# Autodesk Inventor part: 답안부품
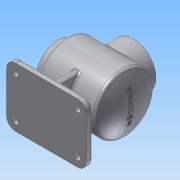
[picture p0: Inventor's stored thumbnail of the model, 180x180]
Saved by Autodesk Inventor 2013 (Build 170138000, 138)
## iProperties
Created: 2016-09
Part Number: 답안부품
Material: 알루미늄 6061
Document SubType Name: Modeling
Designer: Administrator
Density: 2.71 g/cm^3
Mass: 972.013 g
Surface Area: 1284.21 cm^2
Volume: 358.676 cm^3
Author: Administrator
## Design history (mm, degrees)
sketch "스케치1"
  geometry: L1 (-61, 0)-(61, 0); L2 (-61, 38)-(-49, 38); L3 (-49, 38)-(-49, 50); L4 (-49, 50)-(49.562, 50); L5 (-61, 38)-(-61, 27); L6 (47.661, 47)-(-46, 47); L7 (-46, 47)-(-46, 27); L8 (-61, 27)-(-46, 27); A1 r 115 centre (-54, 0) between (61, 0) and (49.562, 50); A2 r 112 centre (-54, 0) between (58, 0) and (47.661, 47); 2 further points
  constraints: 16 end point, 4 point on circle, 3 perpendicular, 2 centre point, 2 coincident, 2 parallel, 1 horizontal, 1 horizontal alignment, 1 midpoint, 1 point on line, 1 vertical alignment
  dimensions: "d0" = 76 diameter of L2 L1; "d2" = 100 diameter of L4 L1; "d3" = 12 distance of L2.start L2.end; "d7" = 115 radius of A1; "d8" = 110 horizontal distance of L1.end L2.end; "d9" = 3 radial gap between concentric circles of A1 A2; "d10" = 3 distance between parallel lines of L4 L6; "d11" = 54 diameter of L8 L1; "d12" = 3 distance between parallel lines of L3 L7
revolve "회전1" sketch "스케치1" stored, may be unused: angle "d13" = 90 deg
chamfer "모따기1" distance "d14" = 1; stored, may be unused: second distance "d15" = 2, angle "d16" = 45 deg
fillet "모깎기1" dims "d17" = 3
fillet "모깎기2" dims "d18" = 5
fillet "모깎기3" dims "d19" = 5
fillet "모깎기4" dims "d20" = 2
sketch "스케치2"
  geometry: C1 r 38 at (0, 0) reference; C2 r 28 at (0, 0) reference; A1 r 32.5 centre (0, 0) between (0, 32.5) and (0, -32.5); 2 further points
  constraints: 4 point on circle, 2 horizontal alignment, 2 vertical alignment, 1 centre point, 1 coincident
  dimensions: "d21" = 65 diameter of A1
hole "구멍1" sketch "스케치2" at (0, 32.5), (0, -32.5), (32.5, 0), (-32.5, 0) diameter "d23" = 3.242; stored, may be unused: countersink angle "d27" = 90 deg, drill point angle "d29" = 118 deg; dims "d24" = 8, "d25" = 4, "d26" = 2, "d28" = 10
node "작업 평면1"
sketch "스케치3"
  geometry: L1 (61, 38)-(61, -38) reference; L2 (49, 45)-(49, -45) reference; C1 r 38 at (-1, 0); 1 further point
  constraints: 1 centre point, 1 horizontal alignment
  dimensions: "d31" = 50 distance from line of C1.centre L2; "d32" = 76 diameter of C1
extrude "돌출1" join sketch "스케치3" stored distance "d33" = 10; taper "d34" = 0 deg
sketch "스케치4"
  geometry: C1 r 38 at (0, 0) reference; C2 r 27 at (0, 0); 1 further point
  constraints: 1 centre point, 1 coincident
  dimensions: "d35" = 54 diameter of C2
extrude "돌출2" cut sketch "스케치4" stored distance "d37" = 10; taper "d38" = 0 deg
fillet "모깎기5" dims "d39" = 3
chamfer "모따기2" distance "d40" = 1; stored, may be unused: second distance "d41" = 2, angle "d42" = 45 deg
sketch "스케치5"
  geometry: C1 r 38 at (0, 0) reference; C2 r 28 at (0, 0) reference; A1 r 32.5 centre (0, 0) between (0, 32.5) and (0, -32.5); 3 further points
  constraints: 4 point on circle, 2 horizontal alignment, 2 vertical alignment, 1 centre point, 1 coincident
  dimensions: "d43" = 65 diameter of A1
hole "구멍2" sketch "스케치5" at (0, 32.5), (0, -32.5), (32.5, 0), (-32.5, 0) diameter "d45" = 3.242; stored, may be unused: countersink angle "d49" = 90 deg, drill point angle "d51" = 118 deg; dims "d46" = 8, "d47" = 4, "d48" = 2, "d50" = 10
node "작업 평면2"
sketch "스케치6"
  geometry: L1 (66.5, 50)-(-68.5, 50); L2 (-68.5, 50)-(-68.5, -50); L3 (-68.5, -50)-(66.5, -50); L4 (66.5, -50)-(66.5, 50); C1 r 1.621 at (-33.5, 0) reference; C2 r 1.621 at (-1, -32.5) reference; C3 r 1.621 at (-1, 32.5) reference; C4 r 1.621 at (31.5, 0) reference; C5 r 38 at (-1, 0) reference; C6 r 28 at (-1, 0) reference
  constraints: 8 end point, 2 parallel, 1 horizontal, 1 perpendicular
  dimensions: "d53" = 135 distance of L1.start L1.end; "d55" = 100 distance of L1.end L2.end; "d56" = 50 distance from line of L3 C5.centre; "d57" = 67.5 distance from line of L2 C5.centre
extrude "돌출3" join sketch "스케치6" distance "d58" = 10; taper "d59" = 0 deg
fillet "모깎기6" dims "d60" = 15
fillet "모깎기7" dims "d61" = 3
sketch "스케치7"
  geometry: C1 r 5 at (-51.5, -35); C2 r 5 at (53.5, -35); C3 r 5 at (53.5, 35); C4 r 5 at (-51.5, 35); A1 r 12 centre (53.5, -35) between (53.5, -47) and (65.5, -35) reference; A2 r 12 centre (53.5, 35) between (65.5, 35) and (53.5, 47) reference; A3 r 12 centre (-51.5, 35) between (-51.5, 47) and (-63.5, 35) reference; A4 r 12 centre (-51.5, -35) between (-63.5, -35) and (-51.5, -47) reference; 1 further point
  constraints: 4 centre point, 4 coincident, 3 equal radius
  dimensions: "d62" = 10 diameter of C4
extrude "돌출4" cut sketch "스케치7" stored distance "d64" = 10; taper "d65" = 0 deg
sketch "스케치8"
  geometry: L1 (-37, 65)-(39, 65) reference; L2 (-51.5, -72)-(53.5, -72) reference; L3 (-44, -50)-(46.374, -50) reference; L4 (-37.075, -50)-(-39, -72); L5 (39.075, -50)-(41, -72); L6 (1, 65)-(1, -138.059); L7 (-39, -72)-(41, -72); A1 r 115 centre (-54, 0) between (50.937, -47.045) and (50.937, 47.045) reference; 1 further point
  constraints: 8 end point, 4 point on line, 2 perpendicular, 1 midpoint
  dimensions: "d66" = 40 distance from line of L4.end L6; "d68" = 40 distance from line of L5.end L6; "d69" = 95 deg angle of L4 L2; "d70" = 95 deg angle of L5 L2
feature "리브1" sketch "스케치8" dims "d71" = 1, "d72" = 10, "d73" = 0, "d74" = 0, "d75" = 1, "d76" = 1
node "작업 평면3"
sketch "스케치9"
  geometry: L1 (8, 146)-(62, 146) reference; L2 (63, 147)-(7, 147) reference; L3 (0, 10)-(70, 10) reference; L4 (-12, 10)-(0, 10) reference; L5 (65, 10)-(75, 10) reference; L6 (70, 10)-(82, 10) reference; L7 (-5, 52)-(-5, 10); 2 further points
  constraints: 2 end point, 1 point on line, 1 vertical, 2 other
  dimensions: "d77" = 40 distance from line of L7 point (35, 82)
feature "리브2" sketch "스케치9" dims "d79" = 1, "d80" = 10, "d81" = 0, "d82" = 0, "d83" = 1, "d84" = 1
sketch "스케치10"
  geometry: L1 (65, 10)-(75, 10) reference; L2 (0, 10)-(70, 10) reference; L3 (70, 10)-(82, 10) reference; L4 (75, 52)-(75, 10); 2 further points
  constraints: 2 end point, 1 perpendicular, 1 point on line, 2 other
  dimensions: "d85" = 40 distance from line of L4 point (35, 82)
feature "리브3" sketch "스케치10" dims "d86" = 1, "d87" = 10, "d88" = 0, "d89" = 0, "d90" = 1, "d91" = 1
fillet "모깎기8" dims "d92" = 3
fillet "모깎기9" dims "d93" = 3
fillet "모깎기10" dims "d94" = 3
node "작업 평면4"
sketch "스케치11"
  geometry: C1 r 47.045 at (0, 0) reference; 2 further points
  constraints: 2 coincident, 1 other
feature "엠보싱1" sketch "스케치11" dims "d18" = 5, "d95" = 0.5, "d96" = 0
node "솔리드1"
node "투영된 루프1"
other parameters: "d30" = 65, "d52" = -82
